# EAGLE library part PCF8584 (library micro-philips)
I2C-Bus CONTROLLER
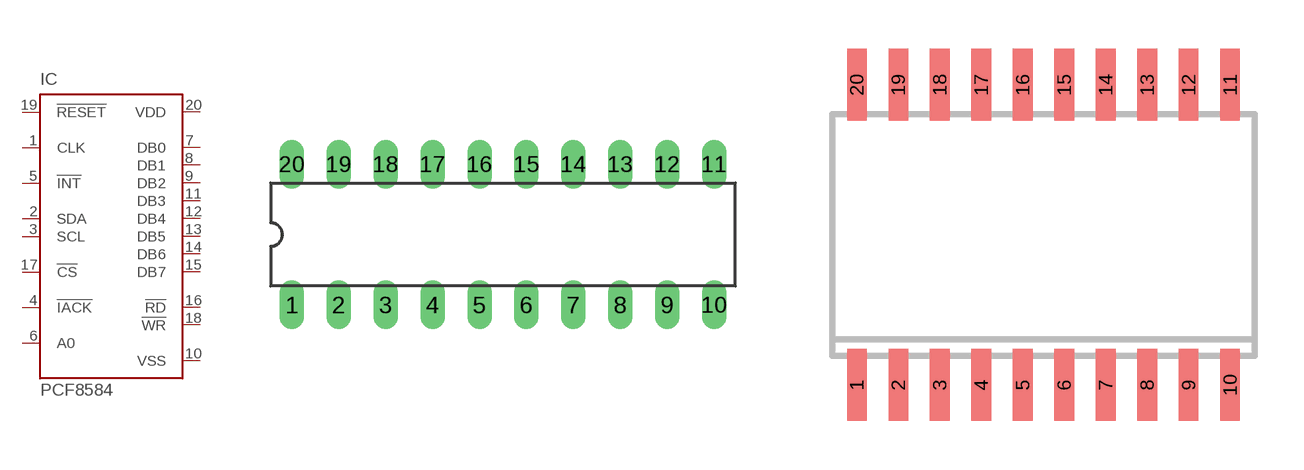
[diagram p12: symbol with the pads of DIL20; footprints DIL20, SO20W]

Designator prefix IC

## PCF8584P (MF: FARNELL; MPN: PCF8584P,112; OC_FARNELL: 8906220; OC_NEWARK: 18K6671)  [DIL20]
1  CLK  in
2  SDA
3  SCL  in
4  !IACK  in
5  !INT  out
6  A0  in
7  DB0
8  DB1
9  DB2
10  VSS  pwr
11  DB3
12  DB4
13  DB5
14  DB6
15  DB7
16  !RD  in
17  !CS  in
18  !WR  in
19  !RESET  in
20  VDD  pwr

## PCF8584T (MPN: PCF8584T/2,512; OC_FARNELL: 1831225; OC_NEWARK: 70R6908)  [SO20W]
Pads as for DIL20

## Footprint DIL20 (pad centres in mm)
Dual In Line
drill 0.813 long: 1 -11.43,-3.81; 2 -8.89,-3.81; 3 -6.35,-3.81; 4 -3.81,-3.81; 5 -1.27,-3.81; 6 1.27,-3.81; 7 3.81,-3.81; 8 6.35,-3.81; 9 8.89,-3.81; 10 11.43,-3.81; 11 11.43,3.81; 12 8.89,3.81; 13 6.35,3.81; 14 3.81,3.81; 15 1.27,3.81; 16 -1.27,3.81; 17 -3.81,3.81; 18 -6.35,3.81; 19 -8.89,3.81; 20 -11.43,3.81

## Footprint SO20W (pad centres in mm)
Small Outline Package 7.6 x 13.2 mm
smd 0.6 x 2.2: 1 -5.715,-4.6; 2 -4.445,-4.6; 3 -3.175,-4.6; 4 -1.905,-4.6; 5 -0.635,-4.6; 6 0.635,-4.6; 7 1.905,-4.6; 8 3.175,-4.6; 9 4.445,-4.6; 10 5.715,-4.6; 11 5.715,4.6; 12 4.445,4.6; 13 3.175,4.6; 14 1.905,4.6; 15 0.635,4.6; 16 -0.635,4.6; 17 -1.905,4.6; 18 -3.175,4.6; 19 -4.445,4.6; 20 -5.715,4.6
